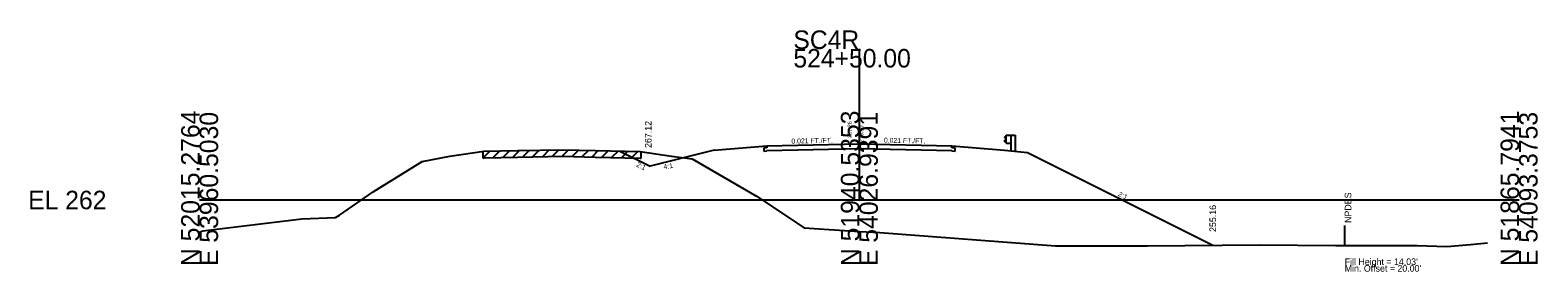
# Model space of a CAD drawing. Extents: x 7498 to 13027, y 90095 to 109625.
# Drawn here: x 9498.3 to 9726.8, y 94594.3 to 94630.8 of the extents above; entities that cross this region are included whole.
import ezdxf

# ---------------------------------------------------------------- set-up
doc = ezdxf.new("R2010")
doc.units = 0
for name, color, linetype in [('Level 10', 7, 'Continuous'), ('Level 11', 7, 'Continuous'), ('Level 12', 7, 'Continuous'), ('Level 24', 7, 'Continuous'), ('Level 32', 7, 'Continuous'), ('Level 33', 7, 'Continuous'), ('Level 50', 7, 'Continuous'), ('Level 55', 7, 'Continuous'), ('Level 59', 7, 'Continuous'), ('Level 6', 7, 'Continuous'), ('Level 60', 7, 'Continuous'), ('Level 61', 7, 'Continuous'), ('Level 63', 7, 'Continuous'), ('Level 7', 7, 'Continuous')]:
    doc.layers.add(name, color=color, linetype=linetype)

msp = doc.modelspace()

# ---------------------------------------------------------------- linework, layer by layer
at = {"layer": 'Level 11'}
for p, q in [((9609.99, 94613.07), (9609.49, 94613.05)), ((9609.49, 94613.05), (9609.49, 94612.57)), ((9609.49, 94612.57), (9609.99, 94612.59)), ((9609.99, 94613.37), (9609.99, 94613.07)), ((9637.99, 94613.07), (9637.99, 94613.37)), ((9638.49, 94613.05), (9637.99, 94613.07)), ((9637.99, 94612.59), (9638.49, 94612.57)), ((9638.49, 94612.57), (9638.49, 94613.05))]:
    msp.add_line(p, q, dxfattribs=at)
at = {"layer": 'Level 12'}
for p, q in [((9623.99, 94612.88), (9609.99, 94612.59)), ((9637.99, 94612.59), (9623.99, 94612.88))]:
    msp.add_line(p, q, dxfattribs=at)
at = {"layer": 'Level 24'}
for p, q in [((9646.26, 94614.88), (9645.99, 94614.68)), ((9645.99, 94614.68), (9645.99, 94614.63)), ((9645.99, 94614.63), (9646.26, 94614.43)), ((9645.99, 94614.1), (9646.26, 94614.3)), ((9646.26, 94613.78), (9646.26, 94614.95)), ((9646.26, 94614.95), (9646.93, 94614.95)), ((9646.93, 94614.95), (9646.93, 94612.6)), ((9646.93, 94614.95), (9647.6, 94614.95)), ((9647.6, 94614.95), (9647.6, 94612.54)), ((9645.99, 94614.05), (9645.99, 94614.1)), ((9646.26, 94613.85), (9645.99, 94614.05)), ((9646.26, 94613.78), (9646.93, 94613.78))]:
    msp.add_line(p, q, dxfattribs=at)
at = {"layer": 'Level 55'}
msp.add_line((9697.56, 94598.32), (9697.56, 94601.32), dxfattribs=at)
at = {"layer": 'Level 59'}
for p, q in [((9609.99, 94613.37), (9623.99, 94613.66)), ((9623.99, 94613.66), (9637.99, 94613.37))]:
    msp.add_line(p, q, dxfattribs=at)
at = {"layer": 'Level 6'}
for p, q in [((9601.99, 94612.7), (9609.99, 94613.37)), ((9637.99, 94613.37), (9645.99, 94612.7)), ((9645.99, 94612.7), (9649.49, 94612.35))]:
    msp.add_line(p, q, dxfattribs=at)
at = {"layer": 'Level 60'}
for p, q in [((9561.92, 94611.81), (9567.06, 94612.52)), ((9567.06, 94612.52), (9572.21, 94612.64)), ((9572.21, 94612.64), (9579.02, 94612.77)), ((9579.02, 94612.77), (9583.98, 94612.64)), ((9583.98, 94612.64), (9590.76, 94612.5)), ((9590.76, 94612.5), (9595.5, 94611.81)), ((9550.27, 94606.38), (9557.74, 94610.98)), ((9557.74, 94610.98), (9561.92, 94611.81)), ((9595.5, 94611.81), (9598.63, 94611.38)), ((9598.63, 94611.38), (9608.42, 94605.73)), ((9545.17, 94602.86), (9550.27, 94606.38)), ((9608.42, 94605.73), (9615.62, 94600.95)), ((9524.48, 94600.5), (9539.5, 94602.3)), ((9539.5, 94602.3), (9544.59, 94602.51)), ((9544.59, 94602.51), (9545.17, 94602.86)), ((9615.62, 94600.95), (9623.99, 94600.42)), ((9523.99, 94600.27), (9524.48, 94600.5)), ((9623.99, 94600.42), (9627.07, 94600.22)), ((9627.07, 94600.22), (9653.72, 94598.21)), ((9667.67, 94598.25), (9684.66, 94598.37)), ((9684.66, 94598.37), (9696.21, 94598.29)), ((9713.06, 94598.13), (9716.61, 94598.41)), ((9716.61, 94598.41), (9719.18, 94598.68)), ((9653.72, 94598.21), (9667.67, 94598.25)), ((9696.21, 94598.29), (9708.56, 94598.29)), ((9708.56, 94598.29), (9713.06, 94598.13))]:
    msp.add_line(p, q, dxfattribs=at)
at = {"layer": 'Level 61'}
for p, q in [((9567.98, 94612.54), (9566.94, 94611.51)), ((9566.94, 94612.51), (9566.94, 94611.51)), ((9569.47, 94612.58), (9568.44, 94611.55)), ((9570.97, 94612.61), (9569.94, 94611.59)), ((9572.47, 94612.64), (9571.44, 94611.62)), ((9573.96, 94612.67), (9572.94, 94611.65)), ((9575.46, 94612.7), (9574.44, 94611.68)), ((9576.96, 94612.73), (9575.94, 94611.71)), ((9578.46, 94612.76), (9577.44, 94611.74)), ((9579.92, 94612.75), (9578.94, 94611.77)), ((9581.42, 94612.71), (9580.44, 94611.73)), ((9582.92, 94612.67), (9581.94, 94611.7)), ((9584.42, 94612.64), (9583.44, 94611.66)), ((9585.92, 94612.6), (9584.94, 94611.62)), ((9587.42, 94612.57), (9586.44, 94611.59)), ((9588.92, 94612.54), (9587.94, 94611.56)), ((9590.42, 94612.5), (9589.44, 94611.53)), ((9590.94, 94611.47), (9590.94, 94612.47)), ((9566.94, 94611.51), (9567.06, 94611.52)), ((9567.06, 94611.52), (9572.21, 94611.64)), ((9572.21, 94611.64), (9579.02, 94611.77)), ((9579.02, 94611.77), (9583.98, 94611.64)), ((9583.98, 94611.64), (9590.76, 94611.5)), ((9590.76, 94611.5), (9590.94, 94611.47))]:
    msp.add_line(p, q, dxfattribs=at)
at = {"layer": 'Level 63'}
for p, q in [((9623.99, 94605.16), (9623.99, 94628)), ((9523.99, 94605.16), (9623.99, 94605.16)), ((9623.99, 94605.16), (9723.99, 94605.16))]:
    msp.add_line(p, q, dxfattribs=at)
at = {"layer": 'Level 7'}
for p, q in [((9587.7, 94612.56), (9592.29, 94610.27)), ((9601.99, 94612.7), (9592.29, 94610.27)), ((9649.49, 94612.35), (9677.56, 94598.32))]:
    msp.add_line(p, q, dxfattribs=at)

# ---------------------------------------------------------------- texts
at = {"layer": 'Level 10'}
msp.add_text('257.26', height=0.6, rotation=90, dxfattribs=at).set_placement((9622.82, 94614.53))
at = {"layer": 'Level 32'}
for s, rotation, p in [('0.021 FT./FT.', 1.1916, (9613.7, 94613.69)), ('0.021 FT./FT.', 358.8084, (9627.71, 94613.83)), ('2:1', 333.435, (9590.1, 94610.28)), ('4:1', 9.4623, (9594.36, 94609.79)), ('2:1', 333.435, (9663.13, 94605.81))]:
    msp.add_text(s, height=0.75, rotation=rotation, dxfattribs=at).set_placement(p)
at = {"layer": 'Level 33'}
for s, p in [('267.12', (9592.49, 94613.03)), ('255.16', (9678.06, 94600.32))]:
    msp.add_text(s, height=1, rotation=90, dxfattribs=at).set_placement(p)
at = {"layer": 'Level 50'}
msp.add_text(' NPDES', height=1, rotation=90, dxfattribs=at).set_placement((9698.56, 94601.32))
for s, p in [("Fill Height = 14.03' ", (9697.56, 94595.32)), ("Min. Offset = 20.00' ", (9697.56, 94594.32))]:
    msp.add_text(s, height=1, dxfattribs=at).set_placement(p)
at = {"layer": 'Level 59'}
msp.add_text(' 270.50', height=0.6, rotation=90, dxfattribs=at).set_placement((9624.59, 94613.66))
at = {"layer": 'Level 63'}
for s, p in [('SC4R', (9613.99, 94628)), ('524+50.00', (9613.99, 94625.2)), ('EL 262', (9498, 94603.76))]:
    msp.add_text(s, height=2.8, dxfattribs=at).set_placement(p)
for s, p in [('N 52015.2764', (9523.99, 94595.16)), ('E 53960.5030', (9526.79, 94595.16)), ('N 51940.5353', (9623.99, 94595.16)), ('E 54026.9391', (9626.79, 94595.16)), ('N 51865.7941', (9723.99, 94595.16)), ('E 54093.3753', (9726.79, 94595.16))]:
    msp.add_text(s, height=2.8, rotation=90, dxfattribs=at).set_placement(p)

doc.saveas('drawing.dxf')
